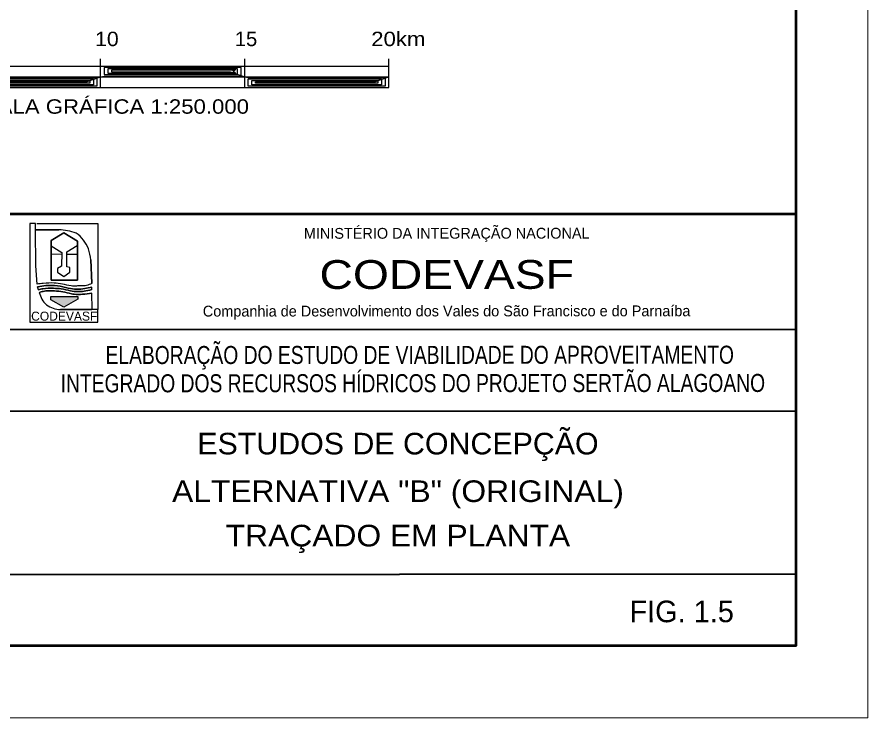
# Model space of a CAD drawing. Extents: x 553962 to 842807, y 8883888 to 9032388.
# Drawn here: x 813277 to 842807, y 8883888 to 8908224 of the extents above; entities that cross this region are included whole.
import ezdxf
from ezdxf.enums import TextEntityAlignment as Align

# ---------------------------------------------------------------- set-up
doc = ezdxf.new("R2010")
doc.units = 0
doc.header["$LTSCALE"] = 200
doc.header["$PDMODE"] = 32
doc.header["$PDSIZE"] = 100
for name, color, linetype, lineweight in [('3', 7, 'Continuous', 13), ('4', 7, 'Continuous', 25), ('5', 7, 'Continuous', 25)]:
    doc.layers.add(name, color=color, linetype=linetype, lineweight=lineweight)

msp = doc.modelspace()

# ---------------------------------------------------------------- hatches: boundary and pattern name
at = {"layer": '4'}
msp.add_hatch(color=256, dxfattribs=at).paths.add_polyline_path([(814449.8, 8898515.3), (815389.8, 8898515.3), (815389.8, 8898430.3), (814904.8, 8898152.8), (814454.8, 8898405.3)])

# ---------------------------------------------------------------- linework, layer by layer
at = {"layer": '3'}
msp.add_lwpolyline([(842807.3, 9032387.8), (842807.3, 8883887.8), (553961.7, 8883887.8), (553961.7, 9032387.8)], close=True, dxfattribs=at)
msp.add_lwpolyline([(842807.3, 9032387.8), (842807.3, 8883887.8), (553961.7, 8883887.8), (553961.7, 9032387.8)], close=True, dxfattribs=at)
at = {"layer": '3', "lineweight": 53}
msp.add_lwpolyline([(840307.3, 9029887.8), (840307.3, 8886387.8), (560211.7, 8886387.8), (560211.7, 9029887.8)], close=True, dxfattribs=at)
msp.add_lwpolyline([(840307.3, 9029887.8), (840307.3, 8886387.8), (560211.7, 8886387.8), (560211.7, 9029887.8)], close=True, dxfattribs=at)
at = {"layer": '4', "lineweight": 40}
for p, q in [((796549.8, 8901392.8), (840297.3, 8901390.3)), ((840297.3, 8901390.3), (840307.3, 8886387.8)), ((840297.3, 8901390.3), (840307.3, 8886387.8)), ((840297.3, 8901390.3), (840307.3, 8886387.8)), ((840307.3, 8901387.8), (840307.3, 8886387.8)), ((840307.3, 8901387.8), (840307.3, 8886387.8)), ((840307.3, 8901387.8), (840307.3, 8886387.8)), ((796552.3, 8897362.8), (840302.3, 8897390.3)), ((812797.3, 8894535.3), (840302.3, 8894555.3)), ((812802.3, 8888870.3), (840304.8, 8888887.8))]:
    msp.add_line(p, q, dxfattribs=at)
at = {"layer": '4', "lineweight": 53}
for p, q in [((796557.3, 8901387.8), (840307.3, 8901387.8)), ((840307.3, 8901387.8), (840307.3, 8886387.8)), ((840307.3, 8901387.8), (840307.3, 8886387.8))]:
    msp.add_line(p, q, dxfattribs=at)
at = {"layer": '4'}
for p, q in [((813919.8, 8900840.3), (814729.8, 8900832.8)), ((814459.8, 8899087.8), (814459.8, 8900460.3)), ((814827.3, 8899980.3), (814467.3, 8899985.3)), ((815367.3, 8899975.3), (815009.8, 8899977.8)), ((815872.3, 8898987.8), (815839.8, 8899792.8)), ((815839.8, 8899792.8), (815872.3, 8898987.8)), ((813992.3, 8898852.8), (814012.3, 8898752.8)), ((814017.3, 8898755.3), (813992.3, 8898852.8)), ((814017.3, 8898755.3), (813992.3, 8898852.8)), ((815869.8, 8898760.3), (815872.3, 8898845.3)), ((815882.3, 8898077.8), (815872.3, 8898637.8)), ((815882.3, 8898077.8), (815872.3, 8898637.8)), ((814784.8, 8898067.8), (815872.3, 8898067.8))]:
    msp.add_line(p, q, dxfattribs=at)
at = {"layer": '4', "lineweight": 53}
msp.add_lwpolyline([(840307.3, 8901387.8), (840307.3, 8886387.8), (796557.3, 8886387.8)], dxfattribs=at)
at = {"layer": '4'}
for points in [[(813919.8, 8901050.3), (813724.8, 8901052.8), (813724.8, 8897632.8), (816079.8, 8897632.8), (816077.3, 8898067.8), (815872.3, 8898067.8), (814784.8, 8898067.8)], [(813919.8, 8901050.3), (813724.8, 8901052.8), (813724.8, 8897632.8), (816079.8, 8897632.8), (816077.3, 8898067.8), (815872.3, 8898067.8), (814784.8, 8898067.8)], [(814729.8, 8900832.8), (813919.8, 8900840.3), (813919.8, 8901050.3)], [(813974.8, 8898952.8), (813929.8, 8899585.3), (813919.8, 8900840.3), (813919.8, 8901050.3)], [(813974.8, 8898952.8), (813929.8, 8899585.3), (813919.8, 8900840.3), (813919.8, 8901050.3)], [(813967.3, 8901052.8), (816079.8, 8901052.8), (816077.3, 8898067.8), (815872.3, 8898067.8)], [(813974.8, 8898952.8), (813929.8, 8899585.3), (813919.8, 8900840.3)], [(814459.8, 8900460.3), (814902.3, 8900735.3), (815374.8, 8900442.8)], [(815374.8, 8900442.8), (814902.3, 8900735.3), (814459.8, 8900460.3), (814459.8, 8899087.8)], [(815374.8, 8900442.8), (815374.8, 8899090.3), (814459.8, 8899087.8)], [(814459.8, 8899087.8), (815374.8, 8899090.3), (815374.8, 8900442.8)], [(814459.8, 8900285.3), (814827.3, 8900047.8), (814822.3, 8899577.8), (814682.3, 8899495.3), (814682.3, 8899362.8), (814902.3, 8899217.8), (815104.8, 8899367.8), (815104.8, 8899527.8), (815009.8, 8899550.3), (815009.8, 8900070.3), (815369.8, 8900287.8)]]:
    msp.add_lwpolyline(points, dxfattribs=at)
msp.add_lwpolyline([(814449.8, 8898515.3), (815389.8, 8898515.3), (815389.8, 8898430.3), (814904.8, 8898152.8), (814454.8, 8898405.3)], close=True, dxfattribs=at)
msp.add_lwpolyline([(814449.8, 8898515.3), (815389.8, 8898515.3), (815389.8, 8898430.3), (814904.8, 8898152.8), (814454.8, 8898405.3)], close=True, dxfattribs=at)
for centre, radius, start, end in [((814701.4, 8898980.4), 1853.2, 70.20108, 89.11971), ((814701.4, 8898980.4), 1853.2, 70.20108, 89.11971), ((814634.9, 8899740.3), 1203.9, 21.25111, 54.78963), ((814634.9, 8899740.3), 1203.9, 21.25111, 54.78963), ((813828.4, 8899561.5), 2024.3, 6.5558, 17.69155), ((813828.4, 8899561.5), 2024.3, 6.5558, 17.69155), ((814799.7, 8898810.8), 763.2, 191.37196, 229.22033), ((814799.7, 8898810.8), 763.2, 191.37196, 229.22033), ((814799.7, 8898810.8), 763.2, 191.37196, 229.22033), ((814812.6, 8898940.3), 872.9, 234.13889, 268.09017), ((814812.6, 8898940.3), 872.9, 234.13889, 268.09017), ((814812.6, 8898940.3), 872.9, 234.13889, 268.09017)]:
    msp.add_arc(centre, radius, start, end, dxfattribs=at)
for points in [[(815872.3, 8898975.3), (815684.8, 8898905.3), (815489.8, 8898887.8), (815342.3, 8898885.3), (815154.8, 8898887.8), (814852.3, 8898950.3), (814564.8, 8898987.8), (814189.8, 8898975.3), (813974.8, 8898952.8)], [(815872.3, 8898975.3), (815684.8, 8898905.3), (815489.8, 8898887.8), (815342.3, 8898885.3), (815154.8, 8898887.8), (814852.3, 8898950.3), (814564.8, 8898987.8), (814189.8, 8898975.3), (813974.8, 8898952.8)], [(815872.3, 8898975.3), (815684.8, 8898905.3), (815489.8, 8898887.8), (815342.3, 8898885.3), (815154.8, 8898887.8), (814852.3, 8898950.3), (814564.8, 8898987.8), (814189.8, 8898975.3), (813974.8, 8898952.8)], [(815872.3, 8898845.3), (815627.3, 8898797.8), (815347.3, 8898772.8), (815057.3, 8898812.8), (814679.8, 8898895.3), (814282.3, 8898897.8), (813992.3, 8898852.8)], [(813992.3, 8898852.8), (814282.3, 8898897.8), (814679.8, 8898895.3), (815057.3, 8898812.8), (815347.3, 8898772.8), (815627.3, 8898797.8), (815872.3, 8898845.3)], [(813992.3, 8898852.8), (814282.3, 8898897.8), (814679.8, 8898895.3), (815057.3, 8898812.8), (815347.3, 8898772.8), (815627.3, 8898797.8), (815872.3, 8898845.3)], [(814012.3, 8898752.8), (814177.3, 8898790.3), (814547.3, 8898805.3), (814812.3, 8898790.3), (815129.8, 8898717.8), (815399.8, 8898692.8), (815602.3, 8898705.3), (815872.3, 8898760.3)], [(815872.3, 8898760.3), (815602.3, 8898705.3), (815399.8, 8898692.8), (815129.8, 8898717.8), (814812.3, 8898790.3), (814547.3, 8898805.3), (814177.3, 8898790.3), (814012.3, 8898752.8)], [(815872.3, 8898760.3), (815602.3, 8898705.3), (815399.8, 8898692.8), (815129.8, 8898717.8), (814812.3, 8898790.3), (814547.3, 8898805.3), (814177.3, 8898790.3), (814012.3, 8898752.8)], [(815872.3, 8898637.8), (815544.8, 8898600.3), (815264.8, 8898600.3), (815162.3, 8898615.3), (814864.8, 8898685.3), (814579.8, 8898712.8), (814179.8, 8898697.8), (814052.3, 8898660.3)], [(814052.3, 8898660.3), (814179.8, 8898697.8), (814579.8, 8898712.8), (814864.8, 8898685.3), (815162.3, 8898615.3), (815264.8, 8898600.3), (815544.8, 8898600.3), (815872.3, 8898637.8)], [(814052.3, 8898660.3), (814179.8, 8898697.8), (814579.8, 8898712.8), (814864.8, 8898685.3), (815162.3, 8898615.3), (815264.8, 8898600.3), (815544.8, 8898600.3), (815872.3, 8898637.8)]]:
    msp.add_spline(points, degree=3, dxfattribs=at)
at = {"layer": '5'}
for p, q in [((816177.5, 8905773.4), (816177.5, 8906773.4)), ((821177.5, 8905773.4), (821177.5, 8906773.4)), ((826177.5, 8905773.4), (826177.5, 8906773.4)), ((806177.5, 8906523.4), (826177.5, 8906523.4)), ((806177.5, 8906149.4), (826177.5, 8906149.4)), ((806177.5, 8905773.4), (826177.5, 8905773.4))]:
    msp.add_line(p, q, dxfattribs=at)
for points in [[(811552.5, 8905973.4), (815677.5, 8905973.4), (816177.5, 8906149.4), (816302.5, 8906173.4), (821052.5, 8906173.4), (821052.5, 8906473.4), (816302.5, 8906473.4), (816302.5, 8906223.4), (820927.5, 8906223.4), (820927.5, 8906423.4), (816427.5, 8906423.4), (816427.5, 8906273.4), (820802.5, 8906273.4), (820802.5, 8906373.4), (816552.5, 8906373.4), (816552.5, 8906323.4), (820677.5, 8906323.4), (821177.5, 8906149.4), (821302.5, 8906123.4), (826052.5, 8906123.4), (826052.5, 8905823.4), (821302.5, 8905823.4), (821302.5, 8906073.4), (825927.5, 8906073.4), (825927.5, 8905873.4), (821427.5, 8905873.4), (821427.5, 8906023.4), (825802.5, 8906023.4), (825802.5, 8905923.4), (821552.5, 8905923.4), (821552.5, 8905973.4), (825677.5, 8905973.4), (826177.5, 8906149.4)], [(811302.5, 8906123.4), (816052.5, 8906123.4), (816052.5, 8905823.4), (811302.5, 8905823.4)], [(811302.5, 8906073.4), (815927.5, 8906073.4), (815927.5, 8905873.4), (811427.5, 8905873.4)], [(811427.5, 8906023.4), (815802.5, 8906023.4), (815802.5, 8905923.4), (811552.5, 8905923.4)]]:
    msp.add_lwpolyline(points, dxfattribs=at)
for p in [(820802.5, 8906398.4), (820802.5, 8906273.4)]:
    msp.add_point(p, dxfattribs=at)

# ---------------------------------------------------------------- texts
at = {"layer": '4'}
for s, height, p in [('MINISTÉRIO DA INTEGRAÇÃO NACIONAL', 374.9, (828189.1, 8900528.4)), ('Companhia de Desenvolvimento dos Vales do São Francisco e do Parnaíba', 375, (828184.4, 8897830.2)), ('FIG. 1.5', 750, (836342.5, 8887212.6))]:
    msp.add_text(s, height=height, rotation=0.034, dxfattribs=at).set_placement(p, align=Align.CENTER)
for s, height, width, p in [('CODEVASF', 1000, 1.2, (828188.7, 8898785.4)), ('ELABORAÇÃO DO ESTUDO DE VIABILIDADE DO APROVEITAMENTO', 625, 0.8, (827252, 8896181.8)), ('INTEGRADO DOS RECURSOS HÍDRICOS DO PROJETO SERTÃO ALAGOANO', 625, 0.8, (827015, 8895200.1))]:
    msp.add_text(s, height=height, rotation=0.034, dxfattribs=dict(at, width=width)).set_placement(p, align=Align.CENTER)
msp.add_text('CODEVASF', height=312.2, dxfattribs=at).set_placement((813767.3, 8897682.8))
for s, width, p in [('ESTUDOS DE CONCEPÇÃO', 1.05, (826496.5, 8893038.7)), ('ALTERNATIVA "B" (ORIGINAL)', 1.1, (826496.5, 8891386.7)), ('TRAÇADO EM PLANTA', 1.1, (826496.5, 8889844.9))]:
    msp.add_text(s, height=750, dxfattribs=dict(at, width=width)).set_placement(p, align=Align.CENTER)
at = {"layer": '5'}
for s, width, p in [('20km', 1.15, (825568.9, 8907213.5)), ('10', 1.1, (815987.1, 8907213.5)), ('15', 1.05, (820832.9, 8907213.5))]:
    msp.add_text(s, height=500, dxfattribs=dict(at, width=width)).set_placement(p)
at = {"layer": '5', "width": 1.15}
msp.add_text('ESCALA GRÁFICA 1:250.000', height=500, dxfattribs=at).set_placement((816177.5, 8904866.8), align=Align.CENTER)

doc.saveas('drawing.dxf')
